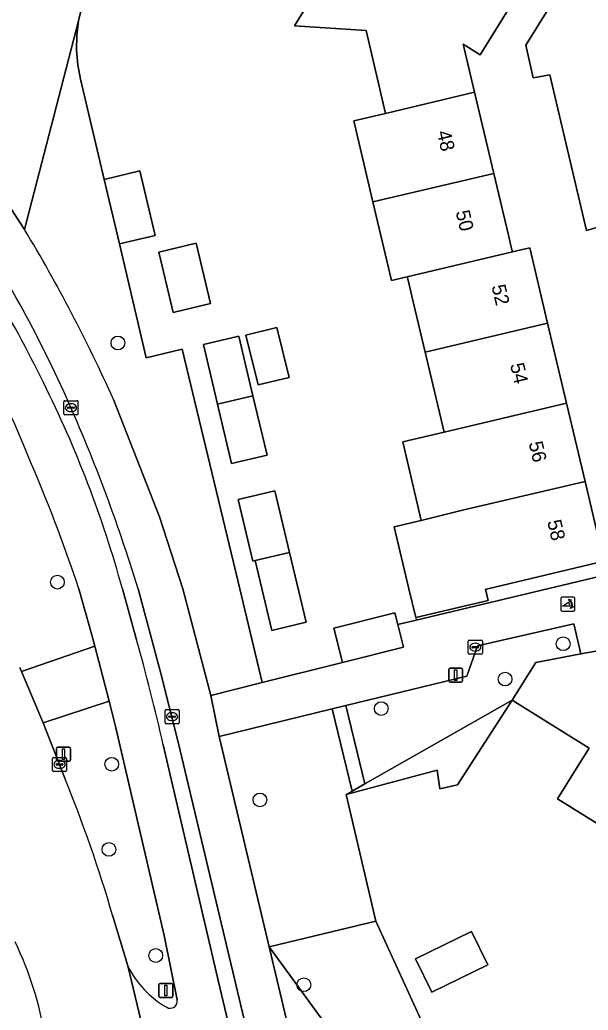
# Model space of a CAD drawing. Extents: x 158031 to 159244, y 380104 to 381214.
# Drawn here: x 158338.5 to 158379, y 380970 to 381040.5 of the extents above; entities that cross this region are included whole.
import ezdxf

# ---------------------------------------------------------------- set-up
doc = ezdxf.new("R2010")
doc.units = 0
for name, color, linetype in [('IMGEO_Berm_groen', 7, 'Continuous'), ('IMGEO_Boom', 7, 'Continuous'), ('IMGEO_Erf', 7, 'Continuous'), ('IMGEO_Fietspad_open', 7, 'Continuous'), ('IMGEO_Groenvoorziening', 7, 'Continuous'), ('IMGEO_Haag', 7, 'Continuous'), ('IMGEO_Kolk', 7, 'Continuous'), ('IMGEO_Lichtmast', 7, 'Continuous'), ('IMGEO_Muur', 7, 'Continuous'), ('IMGEO_Pand', 7, 'Continuous'), ('IMGEO_Pand_nummerreeks', 7, 'Continuous'), ('IMGEO_Poller', 7, 'Continuous'), ('IMGEO_Rijbaan_lokaal_gesloten', 7, 'Continuous'), ('IMGEO_Verkeersbordpaal', 7, 'Continuous'), ('IMGEO_Verkeerseiland_open', 7, 'Continuous'), ('IMGEO_Voetpad_open', 7, 'Continuous')]:
    doc.layers.add(name, color=color, linetype=linetype)

msp = doc.modelspace()

# ---------------------------------------------------------------- linework, layer by layer
at = {"layer": 'IMGEO_Berm_groen'}
for points in [[(158379.556, 381082.426), (158338.208, 381046.187), (158329.502, 381038.556), (158332.361, 381035.036), (158335.701, 381030.36), (158338.863, 381025.561), (158342.715, 381040.382), (158342.953, 381041.398), (158343.297, 381042.385), (158343.742, 381043.33), (158344.283, 381044.223), (158344.915, 381045.055), (158346.143, 381046.275), (158357.382, 381056.336), (158360.887, 381059.398), (158386.519, 381080.758)], [(158338.531, 380994.391), (158338.65, 380994.119), (158343.861, 380995.918), (158343.665, 380996.623), (158342.731, 381000.002)], [(158345.353, 380990.105), (158345.121, 380991.062), (158344.886, 380992.019), (158340.191, 380990.463), (158341.727, 380986.532)], [(158349.718, 380970.772), (158348.788, 380975.334), (158345.353, 380990.105)], [(158345.127, 380976.793), (158346.203, 380973.177)]]:
    msp.add_lwpolyline(points, dxfattribs=at)
for centre, radius, start, end in [((158262.882, 380978.723), 82.194, 21.94732, 32.8981), ((158233.747, 380963.718), 114.865, 18.4143, 23.45806), ((158248.609, 380948.56), 100.563, 16.3048, 22.1846), ((158316.337, 380964.272), 24.299, 9.08426, 25.93295), ((158352.442, 380976.292), 6.974, 206.53159, 240.24218), ((158349.242, 380970.653), 0.49, 237.82219, 14.02891)]:
    msp.add_arc(centre, radius, start, end, dxfattribs=at)
at = {"layer": 'IMGEO_Boom'}
for centre in [(158345.509, 381017.48), (158341.201, 381000.474), (158377.173, 380996.091), (158373.038, 380993.576), (158364.235, 380991.482), (158345.072, 380987.518), (158355.609, 380984.982), (158344.866, 380981.464), (158348.2, 380973.919), (158358.73, 380971.839)]:
    msp.add_circle(centre, 0.489, dxfattribs=at)
at = {"layer": 'IMGEO_Erf'}
for points in [[(158379.965, 381025.816), (158378.84, 381025.492), (158376.222, 381036.559), (158375.028, 381036.327), (158374.512, 381038.654), (158383.116, 381052.496)], [(158374.319, 381042.932), (158371.265, 381037.983), (158370.069, 381038.721), (158370.874, 381035.321), (158372.242, 381029.545), (158373.28, 381025.16), (158373.484, 381024.3), (158373.564, 381023.963), (158374.791, 381024.254), (158376.063, 381018.885), (158377.409, 381013.202), (158378.726, 381007.641), (158380.072, 381001.957), (158371.806, 381000), (158371.655, 380999.964), (158371.841, 380999.176), (158366.684, 380997.955), (158366.2, 381000), (158365.159, 381004.395), (158367.083, 381004.855), (158365.759, 381010.444), (158368.707, 381011.142), (158367.361, 381016.824), (158366.416, 381020.816), (158366.147, 381021.95), (158366.089, 381022.194), (158364.962, 381021.927), (158363.64, 381027.509), (158362.274, 381033.276), (158364.544, 381033.813), (158363.15, 381039.7), (158358.067, 381040.027), (158363.715, 381049.17)], [(158342.953, 381041.398), (158342.715, 381040.382), (158342.583, 381039.345), (158342.561, 381038.301), (158342.648, 381037.26), (158342.844, 381036.234), (158344.527, 381029.119), (158347.075, 381029.722), (158348.163, 381025.128), (158345.615, 381024.524), (158347.508, 381016.416), (158350.088, 381017.039), (158354.175, 381000), (158355.774, 380993.329), (158361.481, 380994.763), (158360.872, 380997.199), (158365.204, 380998.282), (158365.411, 380997.454), (158366.728, 380997.769), (158384.486, 381002.012)], [(158388.202, 380981.177), (158383.521, 380984.09), (158382.068, 380981.757), (158381.916, 380981.852), (158376.77, 380985.055), (158378.223, 380987.388), (158379.02, 380988.668), (158373.553, 380992.071), (158369.656, 380986.051), (158368.397, 380985.783), (158368.206, 380987.105), (158361.742, 380985.372), (158363.858, 380976.351), (158369.389, 380964.254)]]:
    msp.add_lwpolyline(points, dxfattribs=at)
for points in [[(158352.09, 381020.282), (158349.437, 381019.653), (158348.42, 381023.949), (158351.073, 381024.578)], [(158356.819, 381018.579), (158357.678, 381015.032), (158355.475, 381014.498), (158354.616, 381018.045)], [(158355.108, 381013.732), (158356.11, 381009.503), (158353.593, 381008.907), (158352.592, 381013.135), (158351.59, 381017.364), (158354.107, 381017.96)], [(158358.891, 380997.619), (158356.452, 380997.041), (158355.277, 381002.003), (158355.105, 381001.962), (158354.064, 381006.355), (158356.674, 381006.973), (158357.715, 381002.58)], [(158371.815, 380973.262), (158367.833, 380971.316), (158366.676, 380973.686), (158370.657, 380975.631)]]:
    msp.add_lwpolyline(points, close=True, dxfattribs=at)
at = {"layer": 'IMGEO_Fietspad_open'}
for points in [[(158342.731, 381000.002), (158343.665, 380996.623), (158343.861, 380995.918), (158344.886, 380992.019), (158345.121, 380991.062), (158345.353, 380990.105), (158348.788, 380975.334), (158349.718, 380970.772)], [(158346.836, 380996.37), (158345.824, 381000.002)], [(158350.693, 380965.466), (158351.304, 380964.28), (158352.152, 380960.635), (158355.944, 380945.114), (158358.9, 380945.846), (158352.748, 380971.643), (158348.731, 380988.892)], [(158346.203, 380973.177), (158347.272, 380968.737), (158347.509, 380968.78)]]:
    msp.add_lwpolyline(points, dxfattribs=at)
msp.add_lwpolyline([(158340.191, 380990.463), (158344.886, 380992.019), (158343.861, 380995.918), (158338.65, 380994.119)], close=True, dxfattribs=at)
for centre, radius, start, end in [((158229.119, 380959.652), 123.966, 26.34368, 33.44685), ((158262.882, 380978.723), 82.194, 21.94732, 32.8981), ((158267.875, 380978.562), 80.844, 15.37929, 26.52225), ((158233.747, 380963.718), 114.865, 18.4143, 23.45806), ((158212.048, 380958.234), 140.079, 12.6421, 15.79787), ((158352.442, 380976.292), 6.974, 206.53159, 240.24218), ((158349.242, 380970.653), 0.49, 237.82219, 14.02891)]:
    msp.add_arc(centre, radius, start, end, dxfattribs=at)
at = {"layer": 'IMGEO_Groenvoorziening'}
for points in [[(158350.088, 381017.039), (158347.508, 381016.416), (158345.615, 381024.524), (158344.527, 381029.119), (158342.844, 381036.234), (158342.648, 381037.26), (158342.561, 381038.301), (158342.583, 381039.345), (158342.715, 381040.382), (158338.863, 381025.561)], [(158345.198, 381013.46), (158348.465, 381005.126), (158350.127, 381000), (158352.123, 380992.411), (158355.774, 380993.329), (158354.175, 381000), (158350.088, 381017.039)], [(158369.389, 380964.254), (158363.858, 380976.351), (158356.258, 380974.547), (158372.396, 380952.401), (158373.204, 380949.217), (158500, 380979.117), (158570.711, 380995.952)]]:
    msp.add_lwpolyline(points, dxfattribs=at)
for points in [[(158363.069, 380986.125), (158373.553, 380992.071), (158375.227, 380994.759), (158378.43, 380995.367), (158377.92, 380997.519), (158371.074, 380995.938), (158370.312, 380993.796), (158361.707, 380991.691)], [(158361.742, 380985.372), (158368.206, 380987.105), (158368.397, 380985.783), (158369.656, 380986.051), (158373.553, 380992.071), (158363.069, 380986.125), (158362.164, 380985.611)], [(158361.742, 380985.372), (158362.164, 380985.611), (158360.735, 380991.453), (158352.712, 380989.491), (158356.258, 380974.547), (158363.858, 380976.351)], [(158356.258, 380974.547), (158362.848, 380946.775), (158373.204, 380949.217), (158372.396, 380952.401)]]:
    msp.add_lwpolyline(points, close=True, dxfattribs=at)
msp.add_arc((158240.713, 380966.47), 114.565, 24.21497, 31.05009, dxfattribs=at)
at = {"layer": 'IMGEO_Haag'}
for points in [[(158363.069, 380986.125), (158373.553, 380992.071), (158375.227, 380994.759), (158378.43, 380995.367), (158377.92, 380997.519), (158371.074, 380995.938), (158370.312, 380993.796), (158361.707, 380991.691)], [(158363.858, 380976.351), (158361.742, 380985.372), (158362.164, 380985.611), (158360.735, 380991.453), (158352.712, 380989.491), (158356.258, 380974.547)]]:
    msp.add_lwpolyline(points, close=True, dxfattribs=at)
at = {"layer": 'IMGEO_Kolk'}
for p, q in [((158341.668, 381012.452), (158341.668, 381013.304)), ((158341.743, 381013.378), (158342.595, 381013.378)), ((158341.927, 381012.872), (158341.927, 381012.884)), ((158341.97, 381012.921), (158342.368, 381012.921)), ((158342.156, 381013.158), (158342.181, 381013.158)), ((158342.411, 381012.884), (158342.411, 381012.872)), ((158342.669, 381013.304), (158342.669, 381012.452)), ((158342.595, 381012.378), (158341.743, 381012.378)), ((158342.365, 381012.835), (158341.967, 381012.835)), ((158342.179, 381012.598), (158342.154, 381012.598)), ((158370.423, 380995.422), (158370.423, 380996.274)), ((158370.498, 380996.348), (158371.35, 380996.348)), ((158370.911, 380996.128), (158370.936, 380996.128)), ((158371.424, 380996.274), (158371.424, 380995.422)), ((158371.35, 380995.348), (158370.498, 380995.348)), ((158370.682, 380995.842), (158370.682, 380995.854)), ((158371.12, 380995.805), (158370.722, 380995.805)), ((158370.725, 380995.891), (158371.123, 380995.891)), ((158370.934, 380995.568), (158370.909, 380995.568)), ((158371.166, 380995.854), (158371.166, 380995.842)), ((158348.859, 380990.48), (158348.859, 380991.332)), ((158348.934, 380991.406), (158349.786, 380991.406)), ((158349.347, 380991.186), (158349.372, 380991.186)), ((158349.86, 380991.332), (158349.86, 380990.48)), ((158349.786, 380990.406), (158348.934, 380990.406)), ((158349.118, 380990.9), (158349.118, 380990.912)), ((158349.556, 380990.863), (158349.158, 380990.863)), ((158349.161, 380990.949), (158349.559, 380990.949)), ((158349.37, 380990.626), (158349.345, 380990.626)), ((158349.602, 380990.912), (158349.602, 380990.9)), ((158340.857, 380987.085), (158340.857, 380987.937)), ((158340.932, 380988.011), (158341.784, 380988.011)), ((158341.116, 380987.505), (158341.116, 380987.517)), ((158341.159, 380987.554), (158341.557, 380987.554)), ((158341.345, 380987.791), (158341.37, 380987.791)), ((158341.6, 380987.517), (158341.6, 380987.505)), ((158341.858, 380987.937), (158341.858, 380987.085)), ((158341.784, 380987.011), (158340.932, 380987.011)), ((158341.554, 380987.468), (158341.156, 380987.468)), ((158341.368, 380987.231), (158341.343, 380987.231))]:
    msp.add_line(p, q, dxfattribs=at)
for points in [[(158341.668, 381012.452), (158341.668, 381013.304)], [(158341.743, 381013.378), (158342.595, 381013.378)], [(158342.669, 381013.304), (158342.669, 381012.452)], [(158342.595, 381012.378), (158341.743, 381012.378)], [(158370.423, 380995.422), (158370.423, 380996.274)], [(158370.498, 380996.348), (158371.35, 380996.348)], [(158371.424, 380996.274), (158371.424, 380995.422)], [(158371.35, 380995.348), (158370.498, 380995.348)], [(158348.859, 380990.48), (158348.859, 380991.332)], [(158348.934, 380991.406), (158349.786, 380991.406)], [(158349.86, 380991.332), (158349.86, 380990.48)], [(158349.786, 380990.406), (158348.934, 380990.406)], [(158340.857, 380987.085), (158340.857, 380987.937)], [(158340.932, 380988.011), (158341.784, 380988.011)], [(158341.858, 380987.937), (158341.858, 380987.085)], [(158341.784, 380987.011), (158340.932, 380987.011)]]:
    msp.add_lwpolyline(points, dxfattribs=at)
for centre, radius, start, end in [((158341.745, 381013.302), 0.0765, 91.55205, 178.44795), ((158341.745, 381013.302), 0.0765, 91.55205, 178.44795), ((158341.967, 381012.881), 0.0403, 85.87752, 175.75265), ((158341.964, 381012.871), 0.0366, 178.93798, 274.71019), ((158342.368, 381012.878), 0.043, 264.86636, 352.45326), ((158342.372, 381012.883), 0.0386, 1.73085, 96.63898), ((158342.593, 381013.302), 0.0765, 1.55205, 88.44795), ((158342.593, 381013.302), 0.0765, 1.55205, 88.44795), ((158341.745, 381012.454), 0.0765, 181.55205, 268.44795), ((158341.745, 381012.454), 0.0765, 181.55205, 268.44795), ((158342.593, 381012.454), 0.0765, 271.55205, 358.44795), ((158342.593, 381012.454), 0.0765, 271.55205, 358.44795), ((158370.5, 380996.272), 0.0765, 91.55205, 178.44795), ((158370.5, 380996.272), 0.0765, 91.55205, 178.44795), ((158371.348, 380996.272), 0.0765, 1.55205, 88.44795), ((158371.348, 380996.272), 0.0765, 1.55205, 88.44795), ((158370.5, 380995.424), 0.0765, 181.55205, 268.44795), ((158370.5, 380995.424), 0.0765, 181.55205, 268.44795), ((158370.722, 380995.851), 0.0403, 85.87752, 175.75265), ((158370.719, 380995.841), 0.0366, 178.93798, 274.71019), ((158371.123, 380995.848), 0.043, 264.86636, 352.45326), ((158371.127, 380995.853), 0.0386, 1.73085, 96.63898), ((158371.348, 380995.424), 0.0765, 271.55205, 358.44795), ((158371.348, 380995.424), 0.0765, 271.55205, 358.44795), ((158348.936, 380991.33), 0.0765, 91.55205, 178.44795), ((158348.936, 380991.33), 0.0765, 91.55205, 178.44795), ((158349.784, 380991.33), 0.0765, 1.55205, 88.44795), ((158349.784, 380991.33), 0.0765, 1.55205, 88.44795), ((158348.936, 380990.482), 0.0765, 181.55205, 268.44795), ((158348.936, 380990.482), 0.0765, 181.55205, 268.44795), ((158349.158, 380990.909), 0.0403, 85.87752, 175.75265), ((158349.155, 380990.899), 0.0366, 178.93798, 274.71019), ((158349.559, 380990.906), 0.043, 264.86636, 352.45326), ((158349.563, 380990.911), 0.0386, 1.73085, 96.63898), ((158349.784, 380990.482), 0.0765, 271.55205, 358.44795), ((158349.784, 380990.482), 0.0765, 271.55205, 358.44795), ((158340.934, 380987.935), 0.0765, 91.55205, 178.44795), ((158340.934, 380987.935), 0.0765, 91.55205, 178.44795), ((158341.156, 380987.514), 0.0403, 85.87752, 175.75265), ((158341.153, 380987.504), 0.0366, 178.93798, 274.71019), ((158341.557, 380987.511), 0.043, 264.86636, 352.45326), ((158341.561, 380987.516), 0.0386, 1.73085, 96.63898), ((158341.782, 380987.935), 0.0765, 1.55205, 88.44795), ((158341.782, 380987.935), 0.0765, 1.55205, 88.44795), ((158340.934, 380987.087), 0.0765, 181.55205, 268.44795), ((158340.934, 380987.087), 0.0765, 181.55205, 268.44795), ((158341.782, 380987.087), 0.0765, 271.55205, 358.44795), ((158341.782, 380987.087), 0.0765, 271.55205, 358.44795)]:
    msp.add_arc(centre, radius, start, end, dxfattribs=at)
for centre, major_axis, ratio, start_param, end_param in [((158342.155, 381012.878), (-0.387, 0.002), 0.722429, 4.712389, 7.853982), ((158342.18, 381012.878), (-0.39, 0.002), 0.717154, 1.570796, 4.712389), ((158370.91, 380995.848), (-0.387, 0.002), 0.722429, 4.712389, 7.853982), ((158370.935, 380995.848), (-0.39, 0.002), 0.717154, 1.570796, 4.712389), ((158349.346, 380990.906), (-0.387, 0.002), 0.722429, 4.712389, 7.853982), ((158349.371, 380990.906), (-0.39, 0.002), 0.717154, 1.570796, 4.712389), ((158341.344, 380987.511), (-0.387, 0.002), 0.722429, 4.712389, 7.853982), ((158341.369, 380987.511), (-0.39, 0.002), 0.717154, 1.570796, 4.712389)]:
    msp.add_ellipse(centre, major_axis=major_axis, ratio=ratio, start_param=start_param, end_param=end_param, dxfattribs=at)
at = {"layer": 'IMGEO_Lichtmast'}
for p, q in [((158369.029, 380993.453), (158369.029, 380994.253)), ((158369.029, 380994.253), (158369.029, 380993.453)), ((158369.129, 380994.353), (158369.919, 380994.353)), ((158369.919, 380994.353), (158369.129, 380994.353)), ((158370.019, 380994.253), (158370.019, 380993.453)), ((158370.019, 380993.453), (158370.019, 380994.253)), ((158369.919, 380993.353), (158369.129, 380993.353)), ((158369.129, 380993.353), (158369.919, 380993.353)), ((158341.14, 380987.846), (158341.14, 380988.646)), ((158341.14, 380988.646), (158341.14, 380987.846)), ((158341.24, 380988.746), (158342.03, 380988.746)), ((158342.03, 380988.746), (158341.24, 380988.746)), ((158342.13, 380988.646), (158342.13, 380987.846)), ((158342.13, 380987.846), (158342.13, 380988.646)), ((158342.03, 380987.746), (158341.24, 380987.746)), ((158341.24, 380987.746), (158342.03, 380987.746))]:
    msp.add_line(p, q, dxfattribs=at)
for points in [[(158369.449, 380994.228), (158369.599, 380994.228), (158369.599, 380993.478), (158369.449, 380993.478), (158369.449, 380994.228)], [(158341.56, 380988.621), (158341.71, 380988.621), (158341.71, 380987.871), (158341.56, 380987.871), (158341.56, 380988.621)]]:
    msp.add_lwpolyline(points, dxfattribs=at)
for centre, start, end in [((158369.129, 380994.253), 90, 180), ((158369.129, 380994.253), 90, 180), ((158369.919, 380994.253), 0, 90), ((158369.919, 380994.253), 360, 90), ((158369.129, 380993.453), 180, 270), ((158369.129, 380993.453), 180, 270), ((158369.919, 380993.453), 270, 0), ((158369.919, 380993.453), 270, 0), ((158341.24, 380988.646), 90, 180), ((158341.24, 380988.646), 90, 180), ((158342.03, 380988.646), 0, 90), ((158342.03, 380988.646), 360, 90), ((158341.24, 380987.846), 180, 270), ((158341.24, 380987.846), 180, 270), ((158342.03, 380987.846), 270, 0), ((158342.03, 380987.846), 270, 0)]:
    msp.add_arc(centre, 0.1, start, end, dxfattribs=at)
at = {"layer": 'IMGEO_Muur'}
for points in [[(158366.728, 380997.769), (158365.411, 380997.454)], [(158366.684, 380997.955), (158366.728, 380997.769)]]:
    msp.add_lwpolyline(points, dxfattribs=at)
at = {"layer": 'IMGEO_Pand'}
for points in [[(158374.319, 381042.932), (158366.669, 381047.65), (158366.501, 381047.377), (158364.447, 381048.718), (158363.715, 381049.17), (158358.067, 381040.027), (158363.15, 381039.7), (158364.544, 381033.813), (158370.874, 381035.321), (158370.069, 381038.721), (158371.265, 381037.983)], [(158363.64, 381027.509), (158372.242, 381029.545), (158370.874, 381035.321), (158364.544, 381033.813), (158362.274, 381033.276)], [(158345.615, 381024.524), (158348.163, 381025.128), (158347.075, 381029.722), (158344.527, 381029.119)], [(158372.242, 381029.545), (158363.64, 381027.509), (158364.962, 381021.927), (158366.089, 381022.194), (158373.564, 381023.963), (158373.484, 381024.3), (158373.28, 381025.16)], [(158349.437, 381019.653), (158352.09, 381020.282), (158351.073, 381024.578), (158348.42, 381023.949)], [(158373.564, 381023.963), (158366.089, 381022.194), (158366.147, 381021.95), (158366.416, 381020.816), (158367.361, 381016.824), (158376.063, 381018.885), (158374.791, 381024.254)], [(158356.819, 381018.579), (158354.616, 381018.045), (158355.475, 381014.498), (158357.678, 381015.032)], [(158368.707, 381011.142), (158377.409, 381013.202), (158376.063, 381018.885), (158367.361, 381016.824)], [(158352.592, 381013.135), (158355.108, 381013.732), (158354.107, 381017.96), (158351.59, 381017.364)], [(158352.592, 381013.135), (158353.593, 381008.907), (158356.11, 381009.503), (158355.108, 381013.732)], [(158368.707, 381011.142), (158365.759, 381010.444), (158367.083, 381004.855), (158370.024, 381005.581), (158378.726, 381007.641), (158377.409, 381013.202)], [(158378.726, 381007.641), (158370.024, 381005.581), (158367.083, 381004.855), (158365.159, 381004.395), (158366.2, 381000), (158366.684, 380997.955), (158371.841, 380999.176), (158371.655, 380999.964), (158371.806, 381000), (158380.072, 381001.957)], [(158356.674, 381006.973), (158354.064, 381006.355), (158355.105, 381001.962), (158355.277, 381002.003), (158357.715, 381002.58)], [(158357.715, 381002.58), (158355.277, 381002.003), (158356.452, 380997.041), (158358.891, 380997.619)], [(158361.481, 380994.763), (158365.813, 380995.845), (158365.411, 380997.454), (158365.204, 380998.282), (158360.872, 380997.199)], [(158381.916, 380981.852), (158388.006, 380991.635), (158382.946, 380994.785), (158382.478, 380994.031), (158379.887, 380995.644), (158378.43, 380995.367), (158375.227, 380994.759), (158373.553, 380992.071), (158379.02, 380988.668), (158378.223, 380987.388), (158376.77, 380985.055)], [(158367.833, 380971.316), (158371.815, 380973.262), (158370.657, 380975.631), (158366.676, 380973.686)]]:
    msp.add_lwpolyline(points, close=True, dxfattribs=at)
at = {"layer": 'IMGEO_Poller'}
for p, q in [((158376.998, 380999.316), (158376.998, 380998.509)), ((158376.998, 380999.316), (158376.998, 380998.509)), ((158377.9, 380999.411), (158377.092, 380999.411)), ((158377.9, 380999.411), (158377.092, 380999.411)), ((158377.994, 380998.509), (158377.994, 380999.316)), ((158377.994, 380998.509), (158377.994, 380999.316)), ((158377.092, 380998.414), (158377.9, 380998.414)), ((158377.092, 380998.414), (158377.9, 380998.414))]:
    msp.add_line(p, q, dxfattribs=at)
for points in [[(158377.633, 380998.767), (158377.12, 380998.767), (158377.55, 380999.042)], [(158377.677, 380999.14), (158377.665, 380999.067), (158377.54, 380999.272)], [(158377.54, 380999.272), (158377.771, 380999.206), (158377.7, 380999.174)], [(158377.693, 380998.595), (158377.759, 380998.826), (158377.789, 380998.758)], [(158377.825, 380998.731), (158377.897, 380998.72), (158377.693, 380998.595)]]:
    msp.add_lwpolyline(points, dxfattribs=at)
for centre, radius, start, end in [((158377.092, 380999.316), 0.0946, 90, 180), ((158377.092, 380999.316), 0.0946, 90, 180), ((158377.305, 380998.817), 0.332, 351.32473, 42.4854), ((158377.319, 380998.827), 0.476, 351.75274, 41.16905), ((158377.319, 380998.827), 0.516, 349.35686, 42.29123), ((158377.9, 380999.316), 0.0946, 0, 90), ((158377.9, 380999.316), 0.0946, 0, 90), ((158377.092, 380998.509), 0.0946, 180, 270), ((158377.092, 380998.509), 0.0946, 180, 270), ((158377.9, 380998.509), 0.0946, 270, 0), ((158377.9, 380998.509), 0.0946, 270, 0)]:
    msp.add_arc(centre, radius, start, end, dxfattribs=at)
at = {"layer": 'IMGEO_Rijbaan_lokaal_gesloten'}
for points in [[(158341.727, 380986.532), (158340.191, 380990.463), (158338.65, 380994.119), (158338.531, 380994.391)], [(158348.861, 380958.959), (158347.966, 380965.133), (158347.272, 380968.737), (158346.203, 380973.177), (158345.127, 380976.793)]]:
    msp.add_lwpolyline(points, dxfattribs=at)
for centre, radius, start, end in [((158248.609, 380948.56), 100.563, 16.3048, 22.1846), ((158316.337, 380964.272), 24.299, 9.08426, 25.93295)]:
    msp.add_arc(centre, radius, start, end, dxfattribs=at)
at = {"layer": 'IMGEO_Verkeersbordpaal'}
for p, q in [((158348.42, 380971.026), (158348.42, 380971.826)), ((158348.42, 380971.826), (158348.42, 380971.026)), ((158348.52, 380971.926), (158349.31, 380971.926)), ((158349.31, 380971.926), (158348.52, 380971.926)), ((158349.41, 380971.826), (158349.41, 380971.026)), ((158349.41, 380971.026), (158349.41, 380971.826)), ((158349.31, 380970.926), (158348.52, 380970.926)), ((158348.52, 380970.926), (158349.31, 380970.926))]:
    msp.add_line(p, q, dxfattribs=at)
msp.add_lwpolyline([(158348.84, 380971.801), (158348.99, 380971.801), (158348.99, 380971.051), (158348.84, 380971.051), (158348.84, 380971.801)], dxfattribs=at)
for centre, start, end in [((158348.52, 380971.826), 90, 180), ((158348.52, 380971.826), 90, 180), ((158349.31, 380971.826), 0, 90), ((158349.31, 380971.826), 360, 90), ((158348.52, 380971.026), 180, 270), ((158348.52, 380971.026), 180, 270), ((158349.31, 380971.026), 270, 0), ((158349.31, 380971.026), 270, 0)]:
    msp.add_arc(centre, 0.1, start, end, dxfattribs=at)
at = {"layer": 'IMGEO_Verkeerseiland_open'}
for points in [[(158345.824, 381000.002), (158346.836, 380996.37)], [(158348.731, 380988.892), (158352.748, 380971.643), (158358.9, 380945.846), (158359.249, 380945.932), (158359.897, 380946.084), (158356.481, 380961.007), (158349.823, 380989.001), (158348.547, 380994.079), (158346.938, 381000.002)]]:
    msp.add_lwpolyline(points, dxfattribs=at)
for centre, radius, start, end in [((158229.119, 380959.652), 123.966, 26.34368, 33.44685), ((158266.858, 380980.321), 82.04, 24.25279, 35.46834), ((158267.875, 380978.562), 80.844, 15.37929, 26.52225), ((158236.283, 380966.326), 115.666, 16.92666, 24.35197), ((158212.048, 380958.234), 140.079, 12.6421, 15.79787)]:
    msp.add_arc(centre, radius, start, end, dxfattribs=at)
at = {"layer": 'IMGEO_Voetpad_open'}
for points in [[(158383.116, 381052.496), (158374.512, 381038.654), (158375.028, 381036.327), (158376.222, 381036.559), (158378.84, 381025.492), (158379.965, 381025.816)], [(158338.863, 381025.561), (158335.701, 381030.36), (158332.361, 381035.036), (158329.502, 381038.556), (158327.249, 381036.594)], [(158356.258, 380974.547), (158352.712, 380989.491), (158352.123, 380992.411), (158350.127, 381000), (158348.465, 381005.126), (158345.198, 381013.46)], [(158346.938, 381000.002), (158348.547, 380994.079), (158349.823, 380989.001), (158356.481, 380961.007), (158359.897, 380946.084), (158362.848, 380946.775), (158356.258, 380974.547)]]:
    msp.add_lwpolyline(points, dxfattribs=at)
for points in [[(158384.486, 381002.012), (158366.728, 380997.769), (158365.411, 380997.454), (158365.813, 380995.845), (158361.481, 380994.763), (158355.774, 380993.329), (158352.123, 380992.411), (158352.712, 380989.491), (158360.735, 380991.453), (158361.707, 380991.691), (158370.312, 380993.796), (158371.074, 380995.938), (158377.92, 380997.519), (158378.43, 380995.367), (158379.887, 380995.644), (158382.478, 380994.031), (158382.946, 380994.785), (158384.042, 380996.638), (158386.298, 380997.245), (158385.535, 380997.73)], [(158363.069, 380986.125), (158361.707, 380991.691), (158360.735, 380991.453), (158362.164, 380985.611)]]:
    msp.add_lwpolyline(points, close=True, dxfattribs=at)
for centre, radius, start, end in [((158266.858, 380980.321), 82.04, 24.25279, 35.46834), ((158240.713, 380966.47), 114.565, 24.21497, 31.05009), ((158236.283, 380966.326), 115.666, 16.92666, 24.35197)]:
    msp.add_arc(centre, radius, start, end, dxfattribs=at)

# ---------------------------------------------------------------- texts
at = {"layer": 'IMGEO_Pand_nummerreeks'}
for s, rotation, p in [('48', 283.32453, (158368.176, 381032.479)), ('50', 283.32106, (158369.521, 381026.8)), ('52', 283.32679, (158372.068, 381021.519)), ('54', 283.32485, (158373.389, 381015.941)), ('56', 283.32485, (158374.71, 381010.367)), ('58', 283.32485, (158376.03, 381004.79))]:
    msp.add_text(s, height=1, rotation=rotation, dxfattribs=at).set_placement(p)

doc.saveas('drawing.dxf')
